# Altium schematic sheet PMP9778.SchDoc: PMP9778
size A4; Date: Not shown in title block; ApprovedBy: Not shown in title block; CheckedBy: Not shown in title block; Author: Not shown in title block; CompanyName: TI; DrawnBy: Helen Chen; Engineer: Not shown in title block; Organization: Not shown in title block; Address1: Not shown in title block; Address2: Not shown in title block; Address3: Not shown in title block; Address4: Not shown in title block; DocumentNumber: 1; Revision: A; SheetNumber: 1; SheetTotal: 2; PageSetup: Record=PageOptions¦CenterHorizontal=True¦CenterVertical=True¦PrintScale=0.68¦XCorrection=1.00¦YCorrection=1.00¦PrintKind=0¦BorderSize=5000000¦LeftOffset=0¦BottomOffset=0¦Orientation=2¦PaperLength=1000¦PaperWidth=1000¦Scale=100¦PaperSource=15¦PrintQuality=600¦MediaType=1¦DitherType=10¦PrintScaleMode=1¦PaperKind=Letter
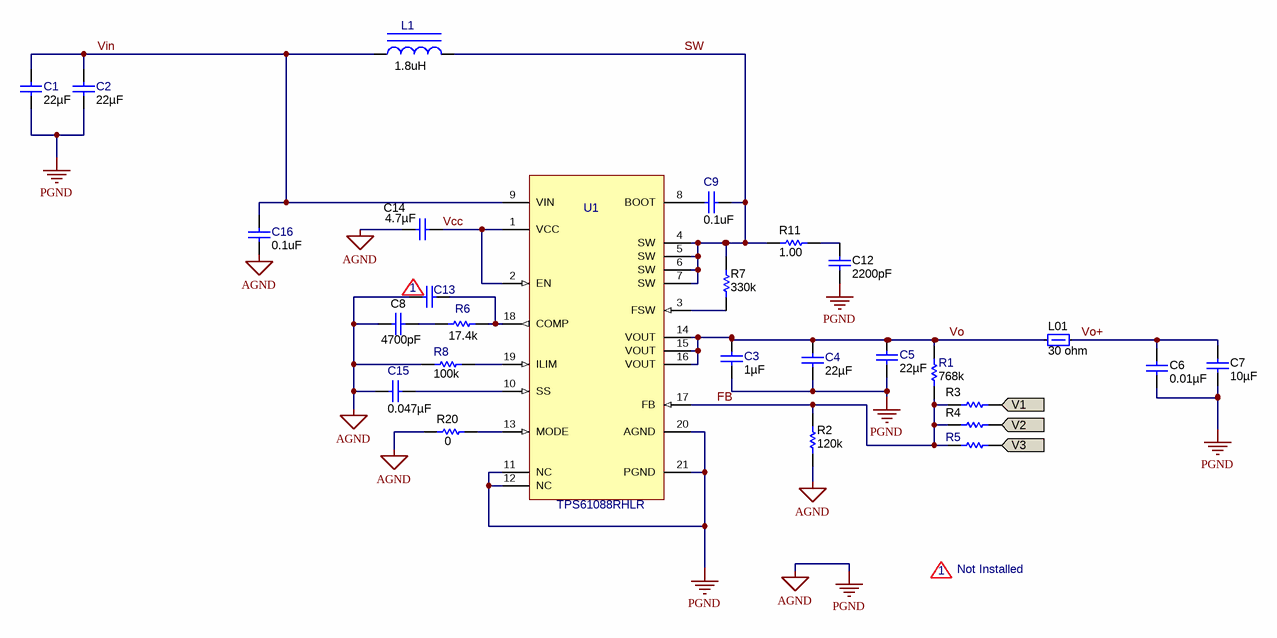
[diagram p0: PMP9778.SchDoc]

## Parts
C1  ValueDisplayed: 22µF  [1206]  (hidden comment: GRM31CR61C226KE15L)
C2  ValueDisplayed: 22µF  [1206]  (hidden comment: GRM31CR61C226KE15L)
C3  ValueDisplayed: 1µF  [0603]  (hidden comment: GRM188R71E105KA12D)
C4  ValueDisplayed: 22µF  [1206]  (hidden comment: GRM31CR61C226KE15L)
C5  ValueDisplayed: 22µF  [1206]  (hidden comment: GRM31CR61C226KE15L)
C6  ValueDisplayed: 0.01µF  [0603]  (hidden comment: GRM188R71E103KA01D)
C7  ValueDisplayed: 10µF  [0805_HV]  (hidden comment: GRM219R61E106KA12)
C8  ValueDisplayed: 4700pF  [0402]  (hidden comment: GRM155R61H472KA01D)
C9  ValueDisplayed: 0.1uF  [0402]  (hidden comment: GRM155R61C104KA88D)
C12  ValueDisplayed: 2200pF  [0603]  (hidden comment: GRM1885C1H222JA01D)
C13  GRM1555C1H470FA01D  [0402]  (value not drawn)
C14  ValueDisplayed: 4.7µF  [0603]  (hidden comment: GRM188R61E475KE11D)
C15  ValueDisplayed: 0.047µF  [0402]  (hidden comment: GRM155R71C473KA01D)
C16  ValueDisplayed: 0.1uF  [0402]  (hidden comment: GRM155R61C104KA88D)
L1  value 1.8uH  [CDMC8D28]  (hidden comment: CDMC8D28NP-1R2MC)
L01  value 30 ohm  [0805_HV]  (hidden comment: MPZ2012S300AT000)
R1  ValueDisplayed: 768k  [0402]  (hidden comment: CRCW0402768KFKED)
R2  ValueDisplayed: 120k  [0402]  (hidden comment: CRCW0402120KFKED)
R3  CRCW0402120KFKED  [0402]  (value not drawn)
R4  CRCW0402120KFKED  [0402]  (value not drawn)
R5  CRCW0402100KFKED  [0402]  (value not drawn)
R6  value 17.4k  [0402]  (hidden comment: CRCW040217K4FKED)
R7  ValueDisplayed: 330k  [0402]  (hidden comment: CRCW0402330KJNED)
R8  value 100k  [0402]  (hidden comment: CRCW0402100KFKED)
R11  ValueDisplayed: 1.00  [0805_HV]  (hidden comment: CRCW08051R00FKEA)
R20  ValueDisplayed: 0  [0402]  (hidden comment: RC0402JR-070RL)
U1  TPS61088RHLR  [RHL0020A]

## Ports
V1, V2, V3

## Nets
AGND: C1.2 C2.2 C3.2 C4.2 C5.2 C6.2 C7.2 C8.2 C12.2 C13.2 C14.2 C15.1 C16.2 R2.1 R8.1 R20.1 U1.11(NC) U1.12(NC) U1.20(AGND) U1.21(PGND)  [also labelled PGND]
FB: R1.1 R2.2 R3.2 R4.2 R5.1 U1.17(FB)
SW: C9.1 L1.2 R7.2 R11.1 U1.4(SW) U1.5(SW) U1.6(SW) U1.7(SW)
V1: R3.1 ; port V1
V2: R4.1 ; port V2
V3: R5.2 ; port V3
Vcc: C14.1 U1.1(VCC) U1.2(EN)
Vin: C1.1 C2.1 C16.1 L1.1 U1.9(VIN)
Vo: C3.1 C4.1 C5.1 L01.1 R1.2 U1.14(VOUT) U1.15(VOUT) U1.16(VOUT)
Vo+: C6.1 C7.1 L01.2
NetC8_1: C8.1 R6.1
NetC9_2: C9.2 U1.8(BOOT)
NetC12_1: C12.1 R11.2
NetC13_1: C13.1 R6.2 U1.18(COMP)
NetC15_2: C15.2 U1.10(SS)
NetR7_1: R7.1 U1.3(FSW)
NetR8_2: R8.2 U1.19(ILIM)
NetR20_2: R20.2 U1.13(MODE)

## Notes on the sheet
- (near C13) 1
- 1
- Not Installed

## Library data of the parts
C1 C2 C4 C5 = GRM31CR61C226KE15L: CAP, CERM, 22 µF, 16 V, +/- 10%, X5R, 1206; Manufacturer: MuRata; Polarized: N; CompType: Capacitor; Value: 22uF; U/M: EA; Cap_F: 0.000022; Tolerance_%: 10; Value1: Unknown; VDC_V: 16; Value2: 16V; TaMin_C: -55; TaMax_C: 85
C3 = GRM188R71E105KA12D: CAP, CERM, 1 µF, 25 V, +/- 10%, X7R, 0603; Manufacturer: MuRata; Polarized: N; CompType: Capacitor; Value: 1uF; U/M: EA; Cap_F: 0.000001; Tolerance_%: 10; Value1: Unknown; VDC_V: 25; Value2: 25V; TaMin_C: -55; TaMax_C: 125
C6 = GRM188R71E103KA01D: CAP, CERM, 0.01 µF, 25 V, +/- 10%, X7R, 0603; Manufacturer: MuRata; Polarized: N; CompType: Capacitor; Value: 0.01uF; U/M: EA; Cap_F: 0.00000001; Tolerance_%: 10; Value1: Unknown; VDC_V: 25; Value2: 25V; TaMin_C: -55; TaMax_C: 125; AEC Category: Q200
C7 = GRM219R61E106KA12: CAP, CERM, 10 µF, 25 V, +/- 10%, X5R, 0805; Manufacturer: MuRata; Polarized: N; CompType: Capacitor; Value: 10uF; U/M: EA; Cap_F: 0.00001; Tolerance_%: 10; Value1: Unknown; VDC_V: 25; Value2: 25V; TaMin_C: -55; TaMax_C: 85; Cap_Case: 0805; AEC Category: Q200
C8 = GRM155R61H472KA01D: CAP, CERM, 4700 pF, 50 V, +/- 10%, X5R, 0402; Manufacturer: MuRata; Polarized: N; CompType: Capacitor; Value: 4700pF; U/M: EA; Cap_F: 0.0000000047; Tolerance_%: 10; Value1: Unknown; VDC_V: 50; Value2: 50V; TaMin_C: -55; TaMax_C: 85
C9 C16 = GRM155R61C104KA88D: CAP, CERM, 0.1uF, 16V, +/-10%, X5R, 0402; Manufacturer: MuRata; Polarized: N; CompType: Capacitor; U/M: EA; Cap_F: 0.0000001; Tolerance_%: 10; Value1: Unknown; VDC_V: 16; TaMin_C: -55; TaMax_C: 85
C12 = GRM1885C1H222JA01D: CAP, CERM, 2200 pF, 50 V, +/- 5%, C0G/NP0, 0603; Manufacturer: MuRata; Polarized: N; CompType: Capacitor; Value: 2200pF; U/M: EA; Cap_F: 0.0000000022; Tolerance_%: 5; Value1: Unknown; VDC_V: 50; Value2: 50V; TaMin_C: -55; TaMax_C: 125; AEC Category: Q200
C13 = GRM1555C1H470FA01D: CAP, CERM, 47 pF, 50 V, +/- 1%, C0G, 0402; Manufacturer: MuRata; Polarized: N; CompType: Capacitor; Value: 47pF; U/M: EA; Cap_F: 0.000000000047; Tolerance_%: 1; Value1: Unknown; VDC_V: 50; Value2: 50V; TaMin_C: -55; TaMax_C: 125
C14 = GRM188R61E475KE11D: CAP, CERM, 4.7 µF, 25 V, +/- 10%, X5R, 0603; Manufacturer: MuRata; Polarized: N; CompType: Capacitor; Value: 4.7uF; U/M: EA; Cap_F: 0.0000047; Tolerance_%: 10; Value1: Unknown; VDC_V: 25; Value2: 25V; TaMin_C: -55; TaMax_C: 85; AEC Category: Q200
C15 = GRM155R71C473KA01D: CAP, CERM, 0.047 µF, 16 V, +/- 10%, X7R, 0402; Manufacturer: MuRata; Polarized: N; CompType: Capacitor; Value: 0.047uF; U/M: EA; Cap_F: 0.000000047; Tolerance_%: 10; Value1: Unknown; VDC_V: 16; Value2: 16V; TaMin_C: -55; TaMax_C: 125
L1 = CDMC8D28NP-1R2MC: Inductor, Shielded Drum Core, Metal Composite, 1.2 µH, 12.9 A, 0.007 ohm, SMD; Manufacturer: Sumida; Ind_H: 1.2E-6; ValueDisplayed: 1.2µH; Imax_A: 12.9; Irms: 12.9A @ 40C rise; Isat: 12.2A @ 20% inductance drop; DCR_ohm: 0.007; Value2: 12.9A; Rule: PcbType=ProtelPcb
L01 = MPZ2012S300AT000: Ferrite Bead, 30 ohm @ 100 MHz, 6 A, 0805; Manufacturer: TDK; Imax_A: 6; DCR_ohm: 0.01; Value1: 0.01 ohm; Value2: 6A; ZTyp@100MHz_Ohm: 30
R1 = CRCW0402768KFKED: RES, 768 k, 1%, 0.063 W, 0402; Manufacturer: Vishay-Dale; CompType: Resistor; Res_ohm: 768000; Value: 768k; Tolerance_%: 1; Power_W: 0.063; Value2: 0.063W; VDC_V: 50; TempCo: 100 ppm/C; EIA_Code: E96; U/M: EA
R2-R4 = CRCW0402120KFKED: RES, 120 k, 1%, 0.063 W, 0402; Manufacturer: Vishay-Dale; CompType: Resistor; Value: 120k; Res_ohm: 120000; Tolerance_%: 1; Power_W: 0.063; Value2: 0.063W; VDC_V: 50; TempCo: 100 ppm/C; U/M: EA
R5 R8 = CRCW0402100KFKED: RES, 100k ohm, 1%, 0.063W, 0402; Manufacturer: Vishay-Dale; CompType: Resistor; Res_ohm: 100000; Tolerance_%: 1; Power_W: 0.063; VDC_V: 50; TempCo: 100 ppm/C; EIA_Code: E96; U/M: EA
R6 = CRCW040217K4FKED: RES, 17.4k ohm, 1%, 0.063W, 0402; Manufacturer: Vishay-Dale; CompType: Resistor; Res_ohm: 17400; Value_Code: 17k4; Tolerance_%: 1; Power_W: 0.063; VDC_V: 50; TempCo: 100 ppm/C; EIA_Code: E96; U/M: EA
R7 = CRCW0402330KJNED: RES, 330 k, 5%, 0.063 W, 0402; Manufacturer: Vishay-Dale; CompType: Resistor; Value: 330k; Res_ohm: 330000; Tolerance_%: 5; Power_W: 0.063; Value2: 0.063W; VDC_V: 50; TempCo: 200 ppm/C; EIA_Code: E24; U/M: EA; AEC Category: Q200
R11 = CRCW08051R00FKEA: RES, 1.00, 1%, 0.125 W, 0805; Manufacturer: Vishay-Dale; CompType: Resistor; Value: 1.00; Res_ohm: 1; Value_Code: 1R00; Power_W: 0.125; Value2: 0.125W; VDC_V: 150; TempCo: 100 ppm/C; EIA_Code: E96; U/M: EA; AEC Category: Q200
R20 = RC0402JR-070RL: RES, 0, 5%, 0.063 W, 0402; Manufacturer: Yageo America; CompType: Resistor; Value: 0; Value_Code: 0000; Tolerance_%: 5; Power_W: 0.063; Value2: 0.063W; VDC_V: 50; TempCo: 200 ppm/C; EIA_Code: E24; U/M: EA; AEC Category: Q200
U1 = TPS61088RHLR: 13.2-V Output, Synchronous Boost Converter with 10-A Switch, RHL0020A; Alternate PartNumber: TPS61088RHLT; Manufacturer: Texas Instruments; SymbolCreator: Altium; CompType: IC; U/M: EA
